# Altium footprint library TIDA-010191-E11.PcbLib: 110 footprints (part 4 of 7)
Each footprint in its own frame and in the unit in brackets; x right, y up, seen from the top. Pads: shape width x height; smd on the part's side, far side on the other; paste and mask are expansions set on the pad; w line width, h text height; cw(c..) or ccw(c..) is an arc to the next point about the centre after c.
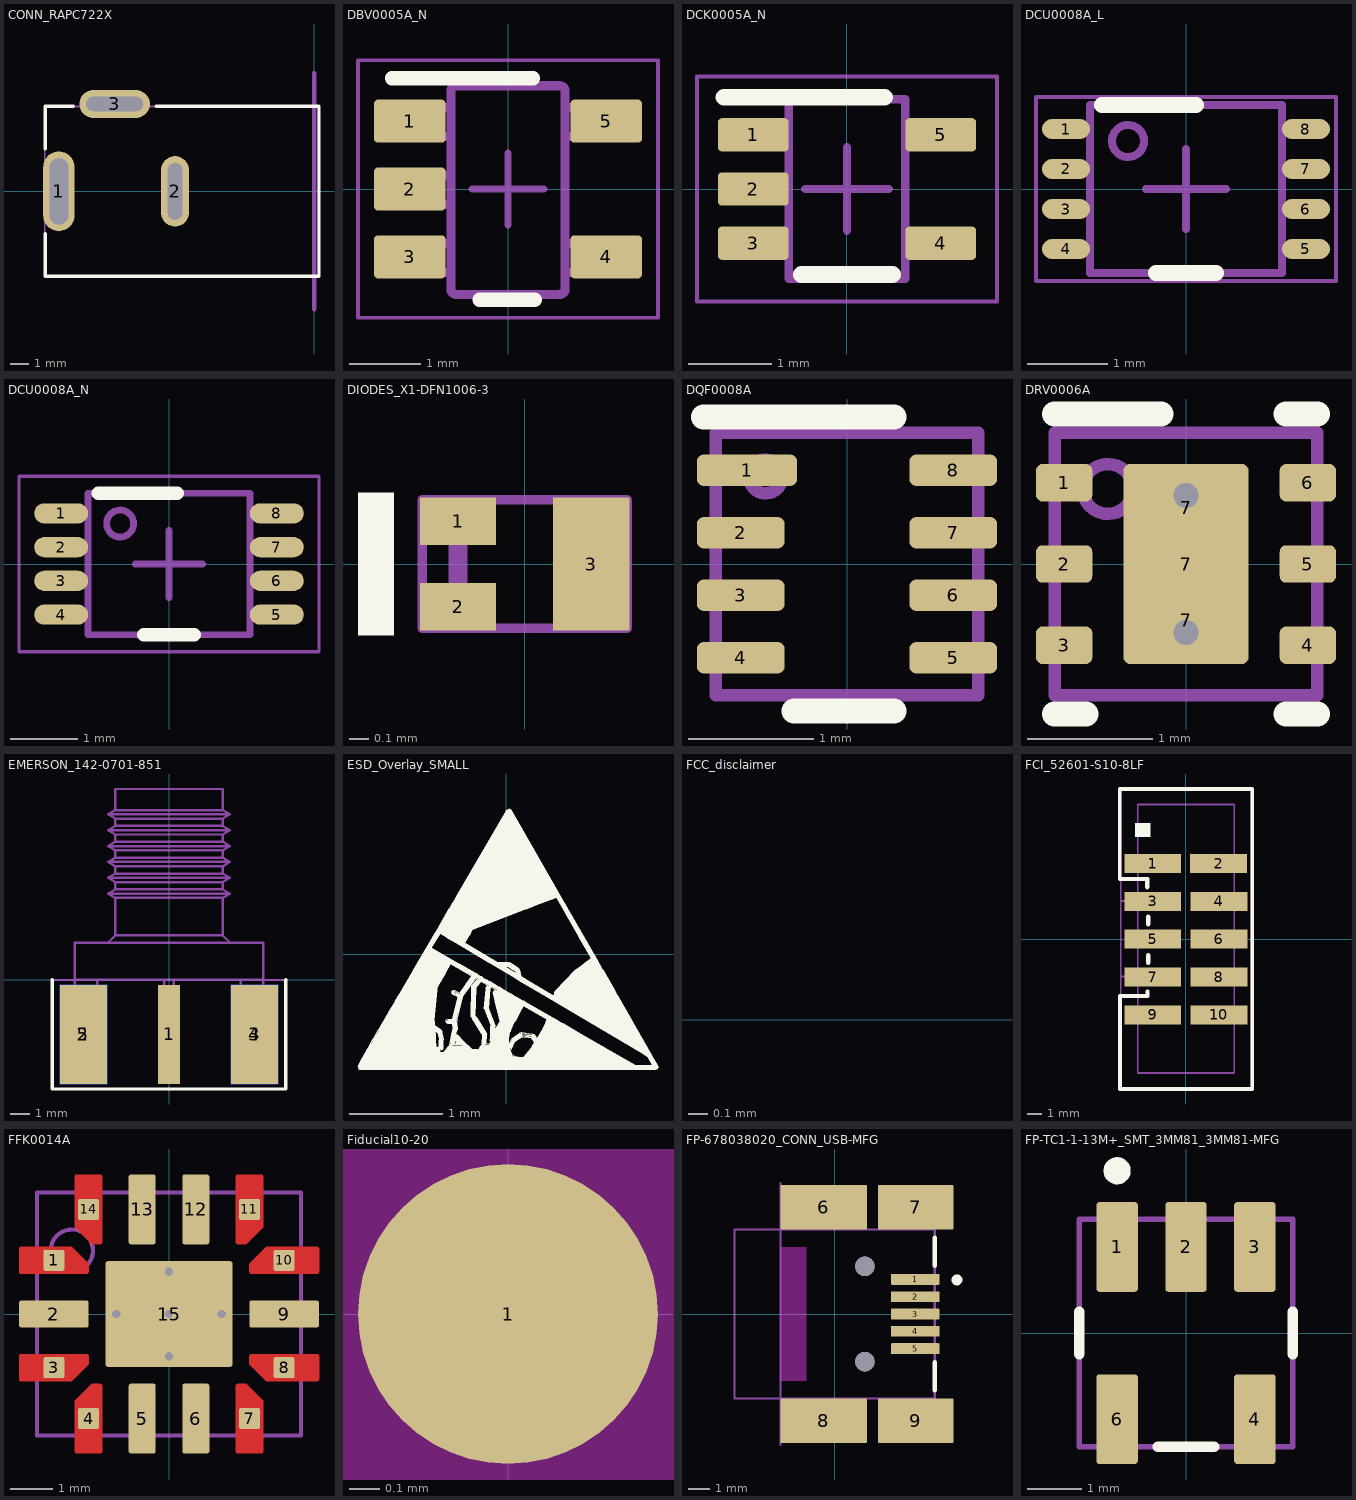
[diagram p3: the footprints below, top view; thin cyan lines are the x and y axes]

## CONN_RAPC722X [mm] "Conn_DC Jack"
height 11.176
pads (3):
  oval 1.7x4.3 hole 1.01 slot 3.56 at 90 deg: 1(-13.741,0)
  oval 1.5x3.8 hole 0.76 slot 3.05 at 90 deg: 2(-7.493,0)
  oval 3.8x1.5 hole 0.76 slot 3.05 at 0 deg: 3(-10.744,4.7)
Top Overlay:
  lines w0.178: -14.478,-2.286 -14.478,-4.572 0.254,-4.572 0.254,4.572 -8.509,4.572 ; -14.478,2.286 -14.478,4.572 -12.954,4.572
Mechanical 1:
  lines w0.254: 0,-6.35 0,6.35
  text "BOARD EDGE" at 1.651,-4.445 h0.89
Mechanical 5:
  lines w0.102: -14.505,-4.572 0.227,-4.572 0.227,4.572 -14.505,4.572 -14.505,-4.572
  lines w0.127: -14.443,-1.5 -13.943,-1.5 ; -14.443,1.5 -13.943,1.5 ; -13.543,-1.5 -13.943,-1.5 ; -13.543,1.5 -13.943,1.5 ; -11.993,4.5 -11.993,4.9 -9.493,4.9 -9.493,4.5 ; -13.943,-1.5 -13.943,1.5
  text ".Designator" at -12.446,-0.508 h1.02
3D body: height 5.08, standoff -2.54, extent -14.06,-1.651 -13.425,1.651
3D body: height 5.08, standoff -2.54, extent -12.14,4.573 -9.346,4.827
3D body: height 5.08, standoff -2.54, extent -7.62,-1.397 -7.366,1.397
3D body: height 11.18, standoff 0, extent -14.504,-4.571 0.226,4.571

## DBV0005A_N [mm] "SOT23, 5-Leads, Body 2.9x1.6mm, Pitch 0.95mm, Lead Span 2.8mm, IPC Medium Density"
height 1.45
pads (5):
  rrect17% 1x0.6 smd: 1(-1.375,0.95) 2(-1.375,0) 3(-1.375,-0.95) 4(1.375,-0.95) 5(1.375,0.95)
Top Overlay:
  lines w0.2: -1.625,1.55 0.35,1.55 ; -0.4,-1.55 0.375,-1.55
Mechanical 5:
  lines w0.127: -0.801,1.371 cw(c-0.725,1.37) -0.725,1.446 ; -0.801,1.37 -0.801,1.371 ; -0.801,1.37 -0.801,-1.399 -0.801,-1.4 ccw(c-0.725,-1.399) -0.725,-1.475 ; -0.725,-1.475 0.723,-1.475 0.724,-1.475 ccw(c0.723,-1.399) 0.799,-1.4 0.799,-1.399 0.799,1.37 ; -0.725,-1.475 -0.725,-1.475 ; -0.725,1.446 -0.725,1.446 ; -0.725,1.446 0.723,1.446 0.724,1.446 cw(c0.723,1.37) 0.799,1.371 ; 0.799,1.37 0.799,1.371 ; -1.423,-1.167 -1.423,-0.767 -1.199,-0.767 -1.105,-0.767 -1.088,-0.767 -0.835,-0.767 -0.801,-0.767 -0.801,-1.167 -0.835,-1.167 -1.088,-1.167 -1.105,-1.167 -1.199,-1.167 -1.423,-1.167 ; -1.423,-0.215 -1.423,0.186 -1.199,0.186 -1.105,0.186 -1.088,0.186 -0.835,0.186 -0.801,0.186 -0.801,-0.215 -0.835,-0.215 -1.088,-0.215 -1.105,-0.215 -1.199,-0.215 -1.423,-0.215 ; -1.423,0.738 -1.423,1.138 -1.199,1.138 -1.105,1.138 -1.088,1.138 -0.835,1.138 -0.801,1.138 -0.801,0.738 -0.835,0.738 -1.088,0.738 -1.105,0.738 -1.199,0.738 -1.423,0.738 ; 0.799,-1.167 0.834,-1.167 1.087,-1.167 1.103,-1.167 1.198,-1.167 1.422,-1.167 1.422,-0.767 1.198,-0.767 1.103,-0.767 1.087,-0.767 0.834,-0.767 0.799,-0.767 0.799,-1.167 ; 0.799,0.738 0.834,0.738 1.087,0.738 1.103,0.738 1.198,0.738 1.422,0.738 1.422,1.138 1.198,1.138 1.103,1.138 1.087,1.138 0.834,1.138 0.799,1.138 0.799,0.738
  text ".Designator" at -0.25,0.95 h0.51
Mechanical 15:
  lines w0.05: -2.1,-1.8 -2.1,1.8 2.1,1.8 2.1,-1.8 -2.1,-1.8
  lines w0.1: -0.5,0 0.5,0 ; 0,-0.5 0,0.5
3D body "DBV0005A.stp": height 1.09, standoff 0, extent -1.422,-1.461 1.423,1.46

## DCK0005A_N [mm] "SOT353, 5-Leads, Body 2x1.3mm, Pitch 0.65mm, Lead Span 2.1mm, IPC Medium Density"
height 1.1
pads (5):
  rrect25% 0.85x0.4 smd: 1(-1.125,0.65) 2(-1.125,0) 3(-1.125,-0.65) 4(1.125,-0.65) 5(1.125,0.65)
Top Overlay:
  lines w0.2: -1.475,1.1 0.45,1.1 ; -0.55,-1.025 0.55,-1.025
Mechanical 5:
  lines w0.1: -0.7,-1.075 0.7,-1.075 0.7,1.075 -0.7,1.075 -0.7,-1.075
  lines w0.127: -0.865,0.762 -0.853,0.762 ; -0.711,-0.763 -0.853,-0.763 -0.865,-0.763 -0.959,-0.763 -1.143,-0.763 -1.143,-0.538 -0.959,-0.538 -0.865,-0.538 -0.853,-0.538 -0.711,-0.538 ; -0.711,-0.113 -0.853,-0.113 -0.865,-0.113 -0.959,-0.113 -1.143,-0.113 -1.143,0.112 -0.959,0.112 -0.865,0.112 -0.853,0.112 -0.711,0.112 ; -0.711,0.537 -0.853,0.537 -0.865,0.537 -0.959,0.537 -1.143,0.537 -1.143,0.762 -0.959,0.762 -0.711,0.762 ; 0.711,-0.763 0.847,-0.763 0.859,-0.763 0.953,-0.763 1.137,-0.763 1.137,-0.538 0.953,-0.538 0.859,-0.538 0.847,-0.538 0.711,-0.538 ; 0.711,0.537 0.847,0.537 0.859,0.537 0.953,0.537 1.137,0.537 1.137,0.762 0.953,0.762 0.859,0.762 0.847,0.762 0.711,0.762
  text ".Designator" at -0.254,0.914 h0.51
Mechanical 15:
  lines w0.05: -1.8,-1.35 1.8,-1.35 1.8,1.35 -1.8,1.35 -1.8,-1.35
  lines w0.1: -0.5,0 0.5,0 ; 0,-0.5 0,0.5
3D body "DCK0005A.stp": height 0.95, standoff 0, extent -1.14,-1 1.14,1

## DCU0008A_L [mm] "TSSOP, 8-Leads, Body 2x2.3mm, Pitch 0.5mm, IPC High Density"
height 0.9
pads (8):
  oval 0.6x0.25 smd: 1(-1.5,0.75) 2(-1.5,0.25) 3(-1.5,-0.25) 4(-1.5,-0.75) 5(1.5,-0.75) 6(1.5,-0.25) 7(1.5,0.25) 8(1.5,0.75)
Top Overlay:
  lines w0.2: -1.05,1.05 0.125,1.05 ; -0.375,-1.05 0.375,-1.05
Mechanical 5:
  circle w0.1: c-0.725,0.6 r0.2
  lines w0.1: -1.2,-1.05 -1.2,1.05 1.2,1.05 1.2,-1.05 -1.2,-1.05
  text ".Designator" at -1.016,-0.489 h0.51
Mechanical 15:
  lines w0.05: -1.875,-1.15 -1.875,1.15 1.875,1.15 1.875,-1.15 -1.875,-1.15
  lines w0.1: -0.5,0 0.5,0 ; 0,-0.5 0,0.5
3D body "DCU0008A.stp": height 0.9, standoff 0, extent -1.561,-1 1.561,1

## DCU0008A_N [mm] "TSSOP, 8-Leads, Body 2x2.3mm, Pitch 0.5mm, IPC Medium Density"
height 0.9
pads (8):
  oval 0.8x0.3 smd: 1(-1.6,0.75) 2(-1.6,0.25) 3(-1.6,-0.25) 4(-1.6,-0.75) 5(1.6,-0.75) 6(1.6,-0.25) 7(1.6,0.25) 8(1.6,0.75)
Top Overlay:
  lines w0.2: -1.05,1.05 0.125,1.05 ; -0.375,-1.05 0.375,-1.05
Mechanical 5:
  circle w0.1: c-0.725,0.6 r0.2
  lines w0.1: -1.2,-1.05 1.2,-1.05 1.2,1.05 -1.2,1.05 -1.2,-1.05
  text ".Designator" at -1.016,-0.489 h0.51
Mechanical 15:
  lines w0.05: -2.225,-1.3 -2.225,1.3 2.225,1.3 2.225,-1.3 -2.225,-1.3
  lines w0.1: -0.5,0 0.5,0 ; 0,-0.5 0,0.5
3D body "DCU0008A.stp": height 0.9, standoff 0, extent -1.561,-1 1.561,1

## DIODES_X1-DFN1006-3 [mm] "Diodes Recommended"
height 0.53
pads (3):
  rect 0.4x0.25 smd: 1(-0.35,0.225) 2(-0.35,-0.225)
  rect 0.4x0.7 smd: 3(0.35,0)
Top Overlay:
  region: -0.875,0.375 -0.687,0.375 -0.687,-0.375 -0.875,-0.375
Mechanical 5:
  rectangle: -0.4,-0.337 -0.3,0.337
  lines w0.05: -0.537,-0.337 -0.537,0.337 0.537,0.337 0.537,-0.337 -0.537,-0.337
  text ".Designator" at -0.225,-0.075 h0.15
3D body: height 0.53, standoff 0.52, extent -0.425,-0.325 -0.35,0.325
3D body: height 0.53, standoff 0, extent -0.537,-0.337 0.537,0.337

## DQF0008A [mm] "SON-8"
height 0.8
pads (8):
  rrect40% 0.8x0.25 smd: 1(-0.8,0.75)
  rrect40% 0.7x0.25 smd: 2(-0.85,0.25) 3(-0.85,-0.25) 4(-0.85,-0.75) 5(0.85,-0.75) 6(0.85,-0.25) 7(0.85,0.25) 8(0.85,0.75)
Top Overlay:
  lines w0.2: -1.15,1.175 0.375,1.175 ; -0.425,-1.175 0.375,-1.175
Mechanical 5:
  circle w0.1: c-0.65,0.7 r0.135
  lines w0.1: -1.05,-1.05 -1.05,1.05 1.05,1.05 1.05,-1.05 -1.05,-1.05
  text ".Designator" at -0.925,-0.25 h0.5
3D body: height 0.8, standoff 0, extent -1.049,-1.049 1.049,1.049
3D body: height 0.81, standoff 0.5, extent -0.784,0.566 -0.516,0.834

## DRV0006A [mm] "SON, 6-Leads, Body 2x2mm, Pitch 0.65mm, Thermal Pad 1.6x1mm, TI Recommended"
height 0.8
pads (9):
  rrect33% 0.45x0.3 smd: 1(-0.975,0.65) 2(-0.975,0) 3(-0.975,-0.65) 4(0.975,-0.65) 5(0.975,0) 6(0.975,0.65)
  rrect50% 1x0.7 on Top Paste: 7(0,-0.45) 7(0,0.45)
  rrect10% 1x1.6 smd paste-0.5: 7(0,0)
via 0,0.55 diameter 0.5 hole 0.2
via 0,-0.55 diameter 0.5 hole 0.2
Top Overlay:
  lines w0.2: -1.05,-1.2 -0.8,-1.2 ; -1.05,1.2 -0.2,1.2 ; 0.8,-1.2 1.05,-1.2 ; 0.8,1.2 1.05,1.2
Mechanical 5:
  circle w0.1: c-0.625,0.6 r0.2
  lines w0.1: -1.05,-1.05 -1.05,1.05 1.05,1.05 1.05,-1.05 -1.05,-1.05
  text ".Designator" at -0.9,-0.5 h0.51
3D body: height 0.8, standoff 0, extent -1.05,-1.05 1.05,1.05
3D body: height 0.81, standoff 0.5, extent -0.824,0.401 -0.426,0.799

## EMERSON_142-0701-851 [mil] "Johnson Components"
height 154
pads (5):
  rect 45x200 smd: 1(0,-110)
  rect 95x200 smd: 2(-172.5,-110) 3(172.5,-110)
  rect 95x200 smd far side: 4(172.5,-110) 5(-172.5,-110)
Top Overlay:
  lines w7: -235,0 -235,-220 -5,-220 235,-220 235,0
Mechanical 1:
  lines w3.94: -235,0 235,0
Mechanical 5:
  lines w5: -145,0 -145,-197 -190,-197 -190,0 ; -123.5,75 -108,90 ; -10,0 -10,-90 10,-90 10,0 ; 123.5,75 108,90 ; 145,0 145,-197 190,-197 190,0 ; -190,0 190,0 ; -190,0 -190,75 190,75 190,0 ; -123,173.9 -108,165.24 ; -123,173.9 -108,182.56 ; -123,173.9 0,173.9 123,173.9 ; -123,205.9 -108,214.56 ; -123,205.9 -108,197.24 ; -123,205.9 0,205.9 123,205.9 ; -123,237.9 -108,229.24 ; -123,237.9 -108,246.56 ; -123,237.9 0,237.9 123,237.9 ; -123,269.9 -108,278.56 ; -123,269.9 -108,261.24 ; -123,269.9 0,269.9 123,269.9 ; -123,301.9 -108,293.24 ; -123,301.9 -108,310.56 ; -123,301.9 0,301.9 123,301.9 ; -123,333.9 -108,325.24 ; -123,333.9 -108,342.56 ; -123,333.9 0,333.9 123,333.9 ; -108,90 -108,165.24 ; -108,90 108,90 ; -108,165.24 108,165.24 ; -108,182.56 -108,197.24 ; -108,182.56 108,182.56 ; -108,197.24 108,197.24 ; -108,214.56 -108,229.24 ; -108,214.56 108,214.56 ; -108,229.24 108,229.24 ; -108,246.56 -108,261.24 ; -108,246.56 108,246.56 ; -108,261.24 108,261.24 ; -108,278.56 -108,293.24 ; -108,278.56 108,278.56 ; -108,293.24 108,293.24 ; -108,310.56 -108,325.24 ; -108,310.56 108,310.56 ; -108,325.24 108,325.24 ; -108,342.56 -108,385 108,385 108,342.56 ; -108,342.56 108,342.56 ; 108,90 108,165.24 ; 108,165.24 123,173.9 ; 108,182.56 123,173.9 ; 108,182.56 108,197.24 ; 108,197.24 123,205.9 ; 108,214.56 123,205.9 ; 108,214.56 108,229.24 ; 108,229.24 123,237.9 ; 108,246.56 108,261.24 ; 108,246.56 123,237.9 ; 108,261.24 123,269.9 ; 108,278.56 108,293.24 ; 108,278.56 123,269.9 ; 108,293.24 123,301.9 ; 108,310.56 123,301.9 ; 108,310.56 108,325.24 ; 108,325.24 123,333.9 ; 108,342.56 123,333.9
  text ".Designator" at -207.2,-186.7 h25
3D body "Johnson_142-0701-851.stp": height 154.6, standoff -162.4, extent -190,-195 190,387

## ESD_Overlay_SMALL [mm]
height 9.53
Top Overlay:
  drawing of 901 lines, arcs and shapes, not listed

## FCC_disclaimer [mm]
height 1.66
Top Overlay:
  text "For evaluation only; not FCC approved for resale." at -15.928,-0.353 h1.52

## FCI_52601-S10-8LF [mil] "FCI Electronics"
height 503
pads (10):
  rect 150x50 smd: 1(-87.5,200) 2(86.5,200) 3(-87.5,100) 4(87.5,100) 5(-87.5,0) 6(87.5,0) 7(-87.5,-100) 8(87.5,-100) 9(-87.5,-200) 10(87.5,-200)
Top Overlay:
  region: -93.2,307.15 -134.24,307.15 -134.24,269.67 -93.2,269.67
  lines w10: -101.5,-138 -101.5,-150 -174,-150 -174,-396 175.5,-396 175.5,397 -174.5,397 -174.5,159 -101.5,159
  lines w12: -101.5,138 -101.5,158 ; -99.5,-62 -99.5,-42 ; -99.5,39 -99.5,59
Mechanical 5:
  lines w5: -172,-99 -127,-99 ; -172,-99 -172,-79 -172,81 -172,101 ; -172,-99 -172,-394 173,-394 173,396 -172,396 -172,101 ; -172,101 -127,101 ; -127,-99 -127,101 ; -127,-99 -127,-354 128,-354 128,356 -127,356 -127,101
  text ".Designator" at -16,165 h30
3D body "FCI_52601-X10-8LF.stp": height 495.6, standoff 0.6, extent -172.5,-395 172.5,395

## FFK0014A [mm] "LCCC-14"
height 1.87
pads (15):
  rrect20% 0.5x0.5 smd: 1(-2.725,1.27) 3(-2.725,-1.27) 4(-1.905,-2.475) 7(1.905,-2.475) 8(2.725,-1.27) 10(2.725,1.27) 11(1.905,2.475) 14(-1.905,2.475)
  rrect16% 1.65x0.64 smd: 2(-2.725,0) 9(2.725,0)
  rrect16% 0.64x1.65 smd: 5(-0.635,-2.475) 6(0.635,-2.475) 12(0.635,2.475) 13(-0.635,2.475)
  rrect4% 3x2.5 smd paste-4: 15(0,0)
via 0,0 diameter 0.5 hole 0.2
via 0,1 diameter 0.5 hole 0.2
via 0,-1 diameter 0.5 hole 0.2
via 1.25,0 diameter 0.5 hole 0.2
via -1.25,0 diameter 0.5 hole 0.2
Top Layer:
  region: -3.5,0.95 -3.51,0.95 -3.528,0.958 -3.542,0.972 -3.55,0.99 -3.55,1 -3.55,1.54 -3.55,1.55 -3.542,1.568 -3.528,1.582 -3.51,1.59 -3.5,1.59 -2.3,1.59 -1.9,1.19 -1.9,1 -1.9,0.99 -1.908,0.972 -1.922,0.958 -1.94,0.95 -1.95,0.95
  region: -3.55,-1.54 -3.55,-1 -3.55,-0.99 -3.542,-0.972 -3.528,-0.958 -3.51,-0.95 -3.5,-0.95 -1.95,-0.95 -1.94,-0.95 -1.922,-0.958 -1.908,-0.972 -1.9,-0.99 -1.9,-1 -1.9,-1.19 -2.3,-1.59 -3.5,-1.59 -3.51,-1.59 -3.528,-1.582 -3.542,-1.568 -3.55,-1.55
  region: -2.225,-3.25 -2.225,-3.26 -2.217,-3.278 -2.203,-3.292 -2.185,-3.3 -2.175,-3.3 -1.635,-3.3 -1.625,-3.3 -1.607,-3.292 -1.593,-3.278 -1.585,-3.26 -1.585,-3.25 -1.585,-1.7 -1.585,-1.69 -1.593,-1.672 -1.607,-1.658 -1.625,-1.65 -1.635,-1.65 -1.825,-1.65 -2.225,-2.05
  region: 1.585,-3.25 1.585,-1.7 1.585,-1.69 1.593,-1.672 1.607,-1.658 1.625,-1.65 1.635,-1.65 1.825,-1.65 2.225,-2.05 2.225,-3.25 2.225,-3.26 2.217,-3.278 2.203,-3.292 2.185,-3.3 2.175,-3.3 1.635,-3.3 1.625,-3.3 1.607,-3.292 1.593,-3.278 1.585,-3.26
  region: 1.9,1 1.9,0.99 1.908,0.972 1.922,0.958 1.94,0.95 1.95,0.95 3.5,0.95 3.51,0.95 3.528,0.958 3.542,0.972 3.55,0.99 3.55,1 3.55,1.54 3.55,1.55 3.542,1.568 3.528,1.582 3.51,1.59 3.5,1.59 2.3,1.59 1.9,1.19
  region: 1.9,-1.19 1.9,-1 1.9,-0.99 1.908,-0.972 1.922,-0.958 1.94,-0.95 1.95,-0.95 3.5,-0.95 3.51,-0.95 3.528,-0.958 3.542,-0.972 3.55,-0.99 3.55,-1 3.55,-1.54 3.55,-1.55 3.542,-1.568 3.528,-1.582 3.51,-1.59 3.5,-1.59 2.3,-1.59
  region: 1.635,1.65 1.625,1.65 1.607,1.658 1.593,1.672 1.585,1.69 1.585,1.7 1.585,3.25 1.585,3.26 1.593,3.278 1.607,3.292 1.625,3.3 1.635,3.3 2.175,3.3 2.185,3.3 2.203,3.292 2.217,3.278 2.225,3.26 2.225,3.25 2.225,2.05 1.825,1.65
  region: -2.225,2.05 -2.225,3.25 -2.225,3.26 -2.217,3.278 -2.203,3.292 -2.185,3.3 -2.175,3.3 -1.635,3.3 -1.625,3.3 -1.607,3.292 -1.593,3.278 -1.585,3.26 -1.585,3.25 -1.585,1.7 -1.585,1.69 -1.593,1.672 -1.607,1.658 -1.625,1.65 -1.635,1.65 -1.825,1.65
Top Paste:
  region: 0.1,-1.15 0.1,-1.16 0.108,-1.178 0.122,-1.192 0.14,-1.2 0.15,-1.2 1.35,-1.2 1.36,-1.2 1.378,-1.192 1.392,-1.178 1.4,-1.16 1.4,-1.15 1.4,-0.15 1.4,-0.14 1.392,-0.122 1.378,-0.108 1.36,-0.1 1.35,-0.1 0.15,-0.1 0.14,-0.1 0.122,-0.108 0.108,-0.122 0.1,-0.14 0.1,-0.15
  region: -1.4,-1.15 -1.4,-0.15 -1.4,-0.14 -1.392,-0.122 -1.378,-0.108 -1.36,-0.1 -1.35,-0.1 -0.15,-0.1 -0.14,-0.1 -0.122,-0.108 -0.108,-0.122 -0.1,-0.14 -0.1,-0.15 -0.1,-1.15 -0.1,-1.16 -0.108,-1.178 -0.122,-1.192 -0.14,-1.2 -0.15,-1.2 -1.35,-1.2 -1.36,-1.2 -1.378,-1.192 -1.392,-1.178 -1.4,-1.16
  region: 0.15,0.1 0.14,0.1 0.122,0.108 0.108,0.122 0.1,0.14 0.1,0.15 0.1,1.15 0.1,1.16 0.108,1.178 0.122,1.192 0.14,1.2 0.15,1.2 1.35,1.2 1.36,1.2 1.378,1.192 1.392,1.178 1.4,1.16 1.4,1.15 1.4,0.15 1.4,0.14 1.392,0.122 1.378,0.108 1.36,0.1 1.35,0.1
  region: -1.4,0.15 -1.4,1.15 -1.4,1.16 -1.392,1.178 -1.378,1.192 -1.36,1.2 -1.35,1.2 -0.15,1.2 -0.14,1.2 -0.122,1.192 -0.108,1.178 -0.1,1.16 -0.1,1.15 -0.1,0.15 -0.1,0.14 -0.108,0.122 -0.122,0.108 -0.14,0.1 -0.15,0.1 -1.35,0.1 -1.36,0.1 -1.378,0.108 -1.392,0.122 -1.4,0.14
Mechanical 5:
  circle w0.1: c-2.3,1.5 r0.5
  lines w0.1: -3.125,-2.875 3.125,-2.875 3.125,2.875 -3.125,2.875 -3.125,-2.875
  text ".Designator" at -2,-0.5 h1.2
3D body "FFK0014A.stp": height 1.63, standoff 0, extent -3,-2.75 3,2.75

## Fiducial10-20 [mm]
height 1.66
pads (1):
  round 1 smd mask+0.5: 1(0,0)
Top Layer keep-out:
  circle w1.178: c0,0 r0.5

## FP-678038020_CONN_USB-MFG [mm]
pads (11):
  rrect20% 2.25x0.5 smd paste+0 mask+0: 1(3.725,1.6) 2(3.725,0.8) 3(3.725,0) 4(3.725,-0.8) 5(3.725,-1.6)
  rrect5% 4x2.05 smd paste+0 mask+0: 6(-0.5,4.925) 8(-0.5,-4.925)
  rrect5% 3.5x2.05 smd paste+0 mask+0: 7(3.75,4.925) 9(3.75,-4.925)
  round 0.9 hole 0.9 unplated paste-1000 mask+0: ""(1.4,-2.2) ""(1.4,2.2)
Top Overlay:
  circle w0.25: c5.65,1.575 r0.125
  lines w0.2: 4.625,-3.525 4.625,-2.225 ; 4.625,2.225 4.625,3.525
Keep-Out Layer:
  rectangle: -2.5,-3.1 -1.3,3.1
Mechanical 5:
  lines w0.1: -2.5,-6.05 -2.5,6.05 ; -4.625,-3.9 4.625,-3.9 4.625,3.9 -4.625,3.9 -4.625,-3.9
  text ".Designator" at 0.437,0 h0.5
3D body "Conn_678038020_CONN_USB.STEP": height 0.25, standoff 0, extent -4.725,-6.05 5.6,6.05

## FP-TC1-1-13M+_SMT_3MM81_3MM81-MFG [mil]
pads (5):
  rrect13% 30x65 smd paste+0 mask+0: 1(-50,62.5) 2(0,62.5) 3(50,62.5) 4(50,-62.5) 6(-50,-62.5)
Top Overlay:
  circle w9.84: c-50,117.81 r4.92
  lines w7.87: -77.5,-15.24 -77.5,15.24 ; -20.24,-82.5 20.24,-82.5 ; 77.5,-15.24 77.5,15.24
Mechanical 5:
  lines w3.94: -77.5,-82.5 77.5,-82.5 77.5,82.5 -77.5,82.5 -77.5,-82.5
  text ".Designator" at 0,0 h19.68
3D body "Trans_TC1-1-13M+_SMT_3MM81_3MM81.STEP": height 10, standoff 0, extent -81.44,-98.94 81.44,98.94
